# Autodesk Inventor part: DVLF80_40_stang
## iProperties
Created: 2010-03
Part Number: DVLF80_40_stang
Document SubType Name: Modeling
Designer: TB
Mass: 462.016 g
Surface Area: 460.605 cm^2
Volume: 462.016 cm^3
Density: 1 g/cm^3
Author: TB
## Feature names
1. Revolution1
2. Fillet1
3. Revolution2
